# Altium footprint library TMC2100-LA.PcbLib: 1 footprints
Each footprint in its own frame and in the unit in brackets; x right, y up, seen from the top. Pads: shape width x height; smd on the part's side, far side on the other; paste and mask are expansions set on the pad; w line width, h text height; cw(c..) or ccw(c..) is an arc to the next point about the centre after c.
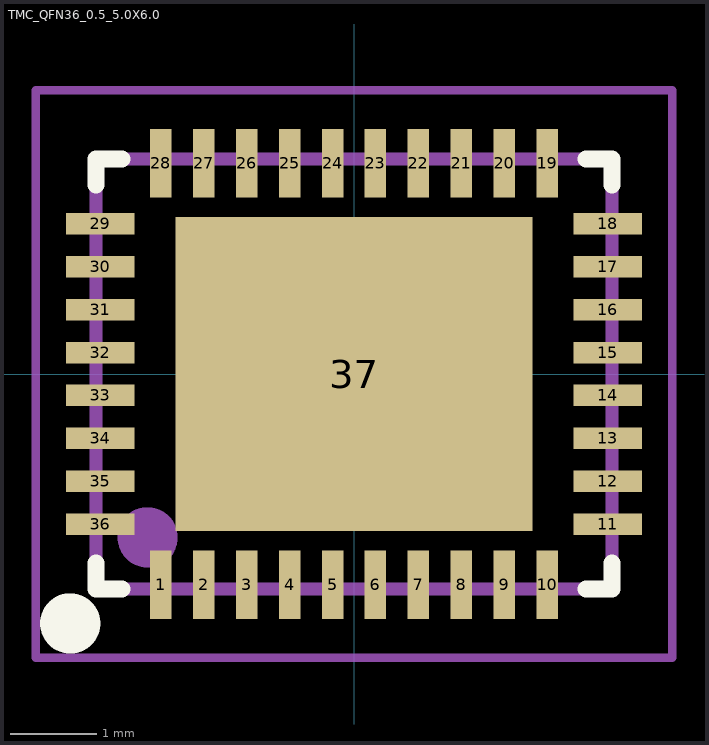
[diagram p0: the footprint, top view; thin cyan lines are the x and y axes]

## TMC_QFN36_0.5_5.0X6.0 [mm]
pads (37):
  rect 0.25x0.8 smd: 1(-2.25,-2.45) 2(-1.75,-2.45) 3(-1.25,-2.45) 4(-0.75,-2.45) 5(-0.25,-2.45) 6(0.25,-2.45) 7(0.75,-2.45) 8(1.25,-2.45) 9(1.75,-2.45) 10(2.25,-2.45) 19(2.25,2.45) 20(1.75,2.45) 21(1.25,2.45) 22(0.75,2.45) 23(0.25,2.45) 24(-0.25,2.45) 25(-0.75,2.45) 26(-1.25,2.45) 27(-1.75,2.45) 28(-2.25,2.45)
  rect 0.8x0.25 smd: 11(2.95,-1.75) 12(2.95,-1.25) 13(2.95,-0.75) 14(2.95,-0.25) 15(2.95,0.25) 16(2.95,0.75) 17(2.95,1.25) 18(2.95,1.75) 29(-2.95,1.75) 30(-2.95,1.25) 31(-2.95,0.75) 32(-2.95,0.25) 33(-2.95,-0.25) 34(-2.95,-0.75) 35(-2.95,-1.25) 36(-2.95,-1.75)
  rect 4.15x3.65 smd paste-25.4 mask-0.025: 37(0,0)
L26-Silk Screen Top (Multiple PADS layers...):
  circle w0.5: c-3.3,-2.9 r0.1
  lines w0.2: -3,-2.2 -3,-2.5 -2.7,-2.5 ; -3,2.2 -3,2.5 -2.7,2.5 ; 2.7,-2.5 3,-2.5 3,-2.2 ; 2.7,2.5 3,2.5 3,2.2
L23-Paste Mask Top (Multiple PADS layers...):
  region: 0.8,-1.5 0.8,-0.3 2,-0.3 2,-1.5
  region: -0.6,-1.5 -0.6,-0.3 0.6,-0.3 0.6,-1.5
  region: -2,-1.5 -2,-0.3 -0.8,-0.3 -0.8,-1.5
  region: 0.8,0.2 0.8,1.4 2,1.4 2,0.2
  region: -0.6,0.2 -0.6,1.4 0.6,1.4 0.6,0.2
  region: -2,0.2 -2,1.4 -0.8,1.4 -0.8,0.2
L13:
  circle w0.5: c-2.4,-1.9 r0.1
  lines w0.15: -3,-2.5 3,-2.5 3,2.5 -3,2.5 -3,-2.5
L15 (Multiple PADS layers...):
  lines w0.1: -3.7,-3.3 3.7,-3.3 3.7,3.3 -3.7,3.3 -3.7,-3.3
